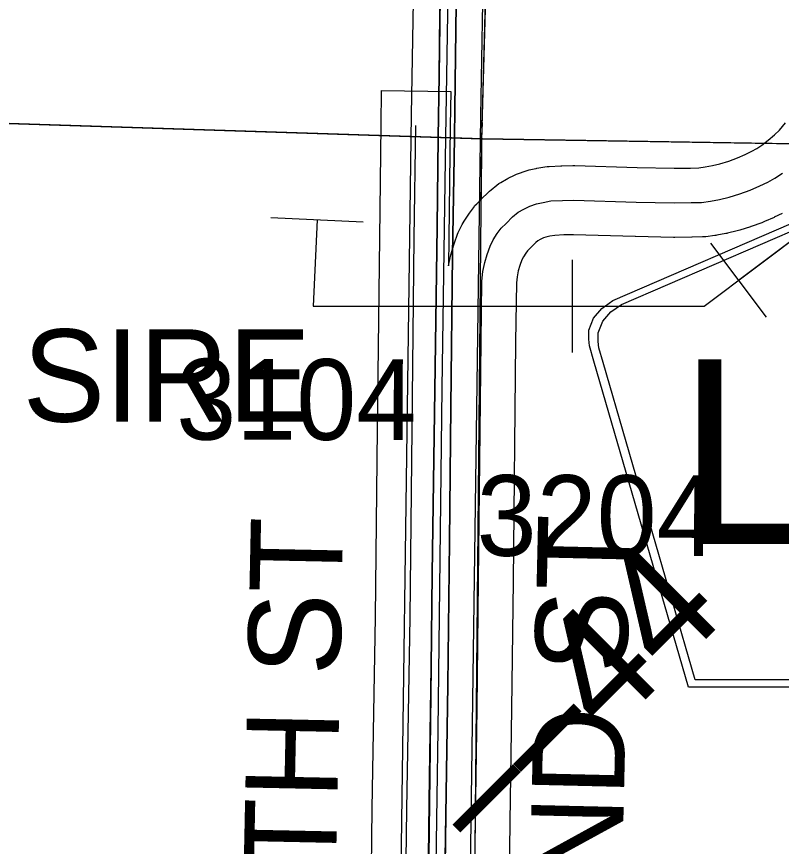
# Model space of a CAD drawing. Extents: x -132.8 to -73.3, y -60 to -26.
# Drawn here: x -121.48 to -120.817, y -55.923 to -55.204 of the extents above; entities that cross this region are included whole.
import ezdxf

# ---------------------------------------------------------------- set-up
doc = ezdxf.new("R2010")
doc.units = 0
for name, color, linetype in [('tdCoCorpBndry', 7, 'Continuous'), ('tdCoDivCarto', 7, 'Continuous'), ('tdCoInt', 7, 'Continuous'), ('tdCoIntCL', 7, 'Continuous'), ('tdCoIntRte', 7, 'Continuous'), ('tdCoPipe', 7, 'Continuous'), ('tdCoPipeTxt', 7, 'Continuous'), ('tdCoPrimary', 7, 'Continuous'), ('tdCoSecRdNmbr', 7, 'Continuous'), ('tdCoSecRdTxt', 7, 'Continuous'), ('tdCoSecRteBand', 7, 'Continuous'), ('tdCoSecRteCL', 7, 'Continuous'), ('tdCoSectLine', 7, 'Continuous'), ('tdCoSectLinePart', 7, 'Continuous'), ('tdCoShieldCoRte', 7, 'Continuous'), ('tdCoSurfAsphalt', 7, 'Continuous'), ('tdCoSurfGravel', 7, 'Continuous'), ('tdCoTwpBndryShd', 7, 'Continuous'), ('tdStHwyIntRefPost1', 7, 'Continuous')]:
    doc.layers.add(name, color=color, linetype=linetype)

msp = doc.modelspace()

# ---------------------------------------------------------------- linework, layer by layer
at = {"layer": 'tdCoCorpBndry'}
msp.add_lwpolyline([(-120.70471, -55.17537), (-120.72184, -55.2041), (-120.75403, -55.25872), (-120.7745, -55.29275), (-120.78919, -55.31424), (-121.07637, -55.30969), (-122.03185, -55.27864), (-122.06321, -55.27827), (-122.07422, -55.18072)], dxfattribs=at)
at = {"layer": 'tdCoDivCarto'}
for p, q in [((-121.11274, -55.15738), (-121.11393, -55.25497)), ((-121.09996, -55.28374), (-121.09875, -55.19277)), ((-121.11393, -55.25497), (-121.11464, -55.3083)), ((-121.10031, -55.30664), (-121.09996, -55.28374)), ((-121.11464, -55.30846), (-121.11566, -55.38567)), ((-121.11464, -55.3083), (-121.11464, -55.30845)), ((-121.11464, -55.30845), (-121.11464, -55.30846)), ((-121.10193, -55.41025), (-121.10035, -55.30892)), ((-121.10035, -55.30892), (-121.10034, -55.3085)), ((-121.10035, -55.30892), (-121.10035, -55.30892)), ((-121.10034, -55.3085), (-121.10031, -55.30664)), ((-121.10034, -55.3085), (-121.10031, -55.30664)), ((-121.11566, -55.38567), (-121.11738, -55.50774)), ((-121.10341, -55.54194), (-121.10193, -55.41025)), ((-121.11738, -55.50774), (-121.11911, -55.6271)), ((-121.10464, -55.65883), (-121.10341, -55.54194)), ((-121.11911, -55.6271), (-121.11985, -55.68678)), ((-121.10612, -55.78312), (-121.10464, -55.65883)), ((-121.11985, -55.68678), (-121.12084, -55.76791)), ((-121.12084, -55.76791), (-121.12207, -55.86261)), ((-121.10785, -55.89582), (-121.10612, -55.78312)), ((-121.12207, -55.86261), (-121.12355, -55.97777)), ((-121.10957, -56.00901), (-121.10785, -55.89582))]:
    msp.add_line(p, q, dxfattribs=at)
for points in [[(-121.11262, -55.14736), (-121.11393, -55.25497), (-121.11464, -55.3083)], [(-121.11262, -55.14736), (-121.11393, -55.25497), (-121.11464, -55.3083)], [(-121.11274, -55.15738), (-121.11393, -55.25497), (-121.11464, -55.3083)], [(-121.10034, -55.3085), (-121.09996, -55.28374), (-121.09875, -55.19277)], [(-121.10034, -55.3085), (-121.09996, -55.28374), (-121.09875, -55.19277)], [(-121.10031, -55.30664), (-121.09996, -55.28374), (-121.09875, -55.19277)], [(-121.11464, -55.30846), (-121.11566, -55.38567), (-121.11738, -55.50774), (-121.11911, -55.6271), (-121.11985, -55.68678), (-121.12084, -55.76791), (-121.12207, -55.86261), (-121.12355, -55.97777), (-121.12503, -56.09713), (-121.12676, -56.2118), (-121.12651, -56.28998), (-121.12644, -56.2918)], [(-121.11464, -55.30846), (-121.11566, -55.38567), (-121.11738, -55.50774), (-121.11911, -55.6271), (-121.11985, -55.68678), (-121.12084, -55.76791), (-121.12207, -55.86261), (-121.12355, -55.97777), (-121.12503, -56.09713), (-121.12676, -56.2118), (-121.12651, -56.28998), (-121.12644, -56.2918)], [(-121.11464, -55.30846), (-121.11566, -55.38567), (-121.11738, -55.50774), (-121.11911, -55.6271), (-121.11985, -55.68678), (-121.12084, -55.76791), (-121.12207, -55.86261), (-121.12355, -55.97777), (-121.12503, -56.09713), (-121.12676, -56.2118), (-121.12651, -56.28998), (-121.12644, -56.2918)], [(-121.11464, -55.3083), (-121.11464, -55.30845), (-121.11464, -55.30846)], [(-121.11464, -55.3083), (-121.11464, -55.30845), (-121.11464, -55.30846)], [(-121.11464, -55.3083), (-121.11464, -55.30845), (-121.11464, -55.30846)], [(-121.11194, -56.29222), (-121.11278, -56.25364), (-121.11155, -56.14933), (-121.10957, -56.00901), (-121.10785, -55.89582), (-121.10612, -55.78312), (-121.10464, -55.65883), (-121.10341, -55.54194), (-121.10193, -55.41025), (-121.10035, -55.30892)], [(-121.11194, -56.29222), (-121.11278, -56.25364), (-121.11155, -56.14933), (-121.10957, -56.00901), (-121.10785, -55.89582), (-121.10612, -55.78312), (-121.10464, -55.65883), (-121.10341, -55.54194), (-121.10193, -55.41025), (-121.10035, -55.30892)], [(-121.11194, -56.29222), (-121.11278, -56.25364), (-121.11155, -56.14933), (-121.10957, -56.00901), (-121.10785, -55.89582), (-121.10612, -55.78312), (-121.10464, -55.65883), (-121.10341, -55.54194), (-121.10193, -55.41025), (-121.10035, -55.30892)], [(-121.10035, -55.30892), (-121.10035, -55.30892), (-121.10034, -55.3085)], [(-121.10035, -55.30892), (-121.10035, -55.30892), (-121.10034, -55.3085)], [(-121.10035, -55.30892), (-121.10035, -55.30892), (-121.10034, -55.3085)]]:
    msp.add_lwpolyline(points, dxfattribs=at)
at = {"layer": 'tdCoInt'}
for points in [[(-121.14184, -56.47033), (-121.14873, -56.31043), (-121.1496, -56.15474), (-121.13788, -55.28894), (-121.13353, -55.04255), (-121.10694, -54.31475)], [(-121.07754, -56.46302), (-121.0866, -56.36086), (-121.08873, -56.30918), (-121.0896, -56.15497), (-121.07788, -55.28991), (-121.07355, -55.04413), (-121.04748, -54.33087)]]:
    msp.add_lwpolyline(points, dxfattribs=at)
at = {"layer": 'tdCoIntCL'}
msp.add_lwpolyline([(-121.11498, -56.39026), (-121.11656, -56.36232), (-121.11786, -56.33063), (-121.11873, -56.3098), (-121.11873, -56.2881), (-121.1196, -56.15486), (-121.11566, -55.88034), (-121.11483, -55.82197), (-121.11135, -55.52597), (-121.10816, -55.30839), (-121.10538, -55.14745), (-121.10354, -55.04334), (-121.09618, -54.83429), (-121.09312, -54.74734), (-121.08618, -54.56897), (-121.0759, -54.28679), (-121.07524, -54.26881), (-121.07524, -54.26881), (-121.06976, -54.11977), (-121.05597, -53.74518), (-121.04104, -53.29303), (-121.03435, -53.13559)], dxfattribs=at)
at = {"layer": 'tdCoIntRte'}
for points in [[(-121.113, -55.14736), (-121.11431, -55.25497), (-121.11501, -55.3083), (-121.11502, -55.30845), (-121.11502, -55.30846), (-121.11604, -55.38567), (-121.11776, -55.50774), (-121.11949, -55.6271), (-121.12023, -55.68678), (-121.12122, -55.76791), (-121.12245, -55.86261), (-121.12393, -55.97777), (-121.12541, -56.09713), (-121.12713, -56.2118), (-121.12689, -56.28813)], [(-121.113, -55.14736), (-121.11431, -55.25497), (-121.11501, -55.3083), (-121.11502, -55.30845), (-121.11502, -55.30846), (-121.11604, -55.38567), (-121.11776, -55.50774), (-121.11949, -55.6271), (-121.12023, -55.68678), (-121.12122, -55.76791), (-121.12245, -55.86261), (-121.12393, -55.97777), (-121.12541, -56.09713), (-121.12713, -56.2118), (-121.12689, -56.28998), (-121.12682, -56.2918)], [(-121.11241, -56.28796), (-121.11316, -56.25364), (-121.11193, -56.14933), (-121.10995, -56.00901), (-121.10823, -55.89582), (-121.1065, -55.78312), (-121.10502, -55.65883), (-121.10379, -55.54194), (-121.10231, -55.41025), (-121.10073, -55.30892), (-121.10073, -55.30892), (-121.10072, -55.3085), (-121.10034, -55.28374), (-121.09913, -55.19277)], [(-121.11232, -56.29222), (-121.11316, -56.25364), (-121.11193, -56.14933), (-121.10995, -56.00901), (-121.10823, -55.89582), (-121.1065, -55.78312), (-121.10502, -55.65883), (-121.10379, -55.54194), (-121.10231, -55.41025), (-121.10073, -55.30892), (-121.10073, -55.30892), (-121.10072, -55.3085), (-121.10034, -55.28374), (-121.09913, -55.19277)]]:
    msp.add_lwpolyline(points, dxfattribs=at)
at = {"layer": 'tdCoPipe'}
for p, q in [((-121.25982, -55.37799), (-121.17974, -55.38163)), ((-120.83007, -55.46438), (-120.87818, -55.40025)), ((-120.99817, -55.49494), (-120.99817, -55.41462))]:
    msp.add_line(p, q, dxfattribs=at)
for points in [[(-121.21972, -55.37981), (-121.22312, -55.45479), (-120.88419, -55.45479), (-120.74793, -55.35255), (-120.59805, -55.35766)], [(-120.85417, -55.43226), (-120.74793, -55.35255), (-120.59805, -55.35766)], [(-121.21972, -55.37981), (-121.22312, -55.45479), (-120.99817, -55.45479)]]:
    msp.add_lwpolyline(points, dxfattribs=at)
at = {"layer": 'tdCoPrimary'}
msp.add_line((-121.10034, -55.3085), (-121.10031, -55.30664), dxfattribs=at)
msp.add_line((-121.10034, -55.3085), (-121.10031, -55.30664), dxfattribs=at)
for points in [[(-121.11274, -55.15738), (-121.11393, -55.25497), (-121.11464, -55.3083), (-121.11464, -55.30845), (-121.11464, -55.30846), (-121.11566, -55.38567), (-121.11738, -55.50774), (-121.11911, -55.6271), (-121.11985, -55.68678), (-121.12084, -55.76791), (-121.12207, -55.86261), (-121.12355, -55.97777), (-121.12503, -56.09713), (-121.12676, -56.2118), (-121.12651, -56.28998), (-121.12644, -56.2918), (-121.12644, -56.2918), (-121.12503, -56.33239), (-121.12209, -56.39006)], [(-121.11274, -55.15738), (-121.11393, -55.25497), (-121.11464, -55.3083)], [(-121.11274, -55.15738), (-121.11393, -55.25497), (-121.11464, -55.3083)], [(-121.10746, -56.39048), (-121.10785, -56.38361), (-121.1113, -56.32171), (-121.11194, -56.29224), (-121.11194, -56.29222), (-121.11278, -56.25364), (-121.11155, -56.14933), (-121.10957, -56.00901), (-121.10785, -55.89582), (-121.10612, -55.78312), (-121.10464, -55.65883), (-121.10341, -55.54194), (-121.10193, -55.41025), (-121.10035, -55.30892), (-121.10035, -55.30892), (-121.10034, -55.3085), (-121.10031, -55.30664), (-121.09996, -55.28374), (-121.09875, -55.19277)], [(-121.10031, -55.30664), (-121.09996, -55.28374), (-121.09875, -55.19277)], [(-121.10031, -55.30664), (-121.09996, -55.28374), (-121.09875, -55.19277)], [(-121.11464, -55.30846), (-121.11566, -55.38567), (-121.11738, -55.50774), (-121.11911, -55.6271), (-121.11985, -55.68678), (-121.12084, -55.76791), (-121.12207, -55.86261), (-121.12355, -55.97777), (-121.12503, -56.09713), (-121.12676, -56.2118), (-121.12651, -56.28998), (-121.12644, -56.2918)], [(-121.11464, -55.30846), (-121.11566, -55.38567), (-121.11738, -55.50774), (-121.11911, -55.6271), (-121.11985, -55.68678), (-121.12084, -55.76791), (-121.12207, -55.86261), (-121.12355, -55.97777), (-121.12503, -56.09713), (-121.12676, -56.2118), (-121.12651, -56.28998), (-121.12644, -56.2918)], [(-121.11464, -55.3083), (-121.11464, -55.30845), (-121.11464, -55.30846)], [(-121.11464, -55.3083), (-121.11464, -55.30845), (-121.11464, -55.30846)], [(-121.11194, -56.29222), (-121.11278, -56.25364), (-121.11155, -56.14933), (-121.10957, -56.00901), (-121.10785, -55.89582), (-121.10612, -55.78312), (-121.10464, -55.65883), (-121.10341, -55.54194), (-121.10193, -55.41025), (-121.10035, -55.30892)], [(-121.11194, -56.29222), (-121.11278, -56.25364), (-121.11155, -56.14933), (-121.10957, -56.00901), (-121.10785, -55.89582), (-121.10612, -55.78312), (-121.10464, -55.65883), (-121.10341, -55.54194), (-121.10193, -55.41025), (-121.10035, -55.30892)], [(-121.10035, -55.30892), (-121.10035, -55.30892), (-121.10034, -55.3085)], [(-121.10035, -55.30892), (-121.10035, -55.30892), (-121.10034, -55.3085)]]:
    msp.add_lwpolyline(points, dxfattribs=at)
at = {"layer": 'tdCoSecRteBand'}
for points in [[(-121.17385, -56.04511), (-121.17188, -55.89036), (-121.17187, -55.89031), (-121.17187, -55.89026), (-121.16916, -55.72438), (-121.16744, -55.56121), (-121.16744, -55.56119), (-121.16744, -55.56117), (-121.16546, -55.39545), (-121.16546, -55.39544), (-121.16546, -55.39543), (-121.16423, -55.29777), (-121.16385, -55.26777), (-121.10386, -55.26853), (-121.10424, -55.29853), (-121.10547, -55.39617), (-121.10575, -55.41985), (-121.1054, -55.41827), (-121.10368, -55.41038), (-121.10345, -55.40932), (-121.10314, -55.40827), (-121.10116, -55.40161), (-121.10089, -55.4007), (-121.10056, -55.39981), (-121.09785, -55.39241), (-121.09727, -55.39083), (-121.09652, -55.38932), (-121.09381, -55.38389), (-121.09311, -55.38251), (-121.09228, -55.3812), (-121.08883, -55.37578), (-121.08828, -55.37491), (-121.08767, -55.37409), (-121.08422, -55.3694), (-121.08288, -55.36759), (-121.08128, -55.36599), (-121.07709, -55.36179), (-121.07142, -55.35612), (-121.07024, -55.35495), (-121.06894, -55.35391), (-121.06401, -55.34996), (-121.06225, -55.34856), (-121.0603, -55.34743), (-121.05562, -55.34471), (-121.05482, -55.34426), (-121.054, -55.34384), (-121.04858, -55.34113), (-121.04685, -55.34027), (-121.04502, -55.33963), (-121.03935, -55.33766), (-121.03763, -55.33706), (-121.03586, -55.33668), (-121.03019, -55.33544), (-121.02964, -55.33532), (-121.02909, -55.33523), (-121.02219, -55.33399), (-121.02029, -55.33366), (-121.01837, -55.33356), (-121.00826, -55.33307), (-121.00792, -55.33305), (-121.00757, -55.33304), (-120.99795, -55.3328), (-120.99709, -55.33277), (-120.99623, -55.3328), (-120.94211, -55.33452), (-120.91004, -55.33525), (-120.896, -55.33501), (-120.88874, -55.33481), (-120.88319, -55.33412), (-120.87688, -55.33293), (-120.87037, -55.3314), (-120.86277, -55.32894), (-120.85524, -55.32629), (-120.84843, -55.32319), (-120.84266, -55.32052), (-120.83851, -55.31819), (-120.83396, -55.31516), (-120.82871, -55.31092), (-120.82303, -55.30626), (-120.81888, -55.30211), (-120.8135, -55.29593)], [(-120.81636, -55.37446), (-120.82327, -55.37767), (-120.82338, -55.37772), (-120.82349, -55.37777), (-120.83163, -55.38147), (-120.83284, -55.38202), (-120.8341, -55.38246), (-120.84322, -55.38566), (-120.84356, -55.38579), (-120.84391, -55.3859), (-120.85303, -55.38886), (-120.85421, -55.38924), (-120.85542, -55.38952), (-120.8638, -55.3915), (-120.86447, -55.39165), (-120.86515, -55.39178), (-120.87304, -55.39326), (-120.87394, -55.39343), (-120.87484, -55.39354), (-120.88274, -55.39453), (-120.88417, -55.39471), (-120.88562, -55.39475), (-120.8945, -55.39499), (-120.89467, -55.395), (-120.89484, -55.395), (-120.90963, -55.39525), (-120.91022, -55.39526), (-120.91081, -55.39524), (-120.94361, -55.3945), (-120.94375, -55.3945), (-120.94388, -55.3945), (-120.99728, -55.3928), (-121.00569, -55.39301), (-121.01353, -55.3934), (-121.01799, -55.39419), (-121.02134, -55.39492), (-121.02348, -55.39566), (-121.02635, -55.3971), (-121.02829, -55.39822), (-121.03017, -55.39972), (-121.03466, -55.40422), (-121.03726, -55.40682), (-121.03876, -55.40886), (-121.04083, -55.41211), (-121.0421, -55.41465), (-121.0439, -55.41957), (-121.0453, -55.42427), (-121.04638, -55.42923), (-121.04686, -55.4346), (-121.04758, -55.48572), (-121.0498, -55.69307), (-121.0498, -55.69307), (-121.0498, -55.69308), (-121.05103, -55.80381), (-121.05103, -55.80387), (-121.05103, -55.80393), (-121.05251, -55.90155), (-121.05473, -56.07488)]]:
    msp.add_lwpolyline(points, dxfattribs=at)
at = {"layer": 'tdCoSecRteCL'}
for points in [[(-121.14765, -56.29087), (-121.14875, -56.25809), (-121.14702, -56.1957), (-121.14385, -56.04562), (-121.14188, -55.89075), (-121.13917, -55.72478), (-121.13744, -55.56153), (-121.13547, -55.39581), (-121.13423, -55.29815)], [(-121.08473, -56.07449), (-121.08251, -55.90113), (-121.08103, -55.80347), (-121.0798, -55.69275), (-121.07758, -55.48535), (-121.07684, -55.43307), (-121.0761, -55.42468), (-121.07437, -55.41679), (-121.0724, -55.41013), (-121.06969, -55.40274), (-121.06697, -55.39731), (-121.06352, -55.39189), (-121.06007, -55.3872), (-121.05588, -55.38301), (-121.0502, -55.37734), (-121.04527, -55.37339), (-121.04059, -55.37068), (-121.03516, -55.36797), (-121.02949, -55.36599), (-121.02382, -55.36476), (-121.01691, -55.36353), (-121.0068, -55.36303), (-120.99718, -55.36279), (-120.94293, -55.36451), (-120.91013, -55.36525), (-120.89534, -55.36501), (-120.88646, -55.36476), (-120.87857, -55.36377), (-120.87067, -55.36229), (-120.86229, -55.36032), (-120.85317, -55.35736), (-120.84404, -55.35415), (-120.8359, -55.35046), (-120.829, -55.34725), (-120.82283, -55.3438), (-120.81617, -55.33936)]]:
    msp.add_lwpolyline(points, dxfattribs=at)
at = {"layer": 'tdCoSectLine'}
for points in [[(-121.07675, -55.30969), (-121.05003, -54.29547)], [(-122.03223, -55.27864), (-121.07675, -55.30969)], [(-121.08617, -56.293), (-121.07675, -55.30969)], [(-121.07675, -55.30969), (-120.07349, -55.32557)]]:
    msp.add_lwpolyline(points, dxfattribs=at)
at = {"layer": 'tdCoSectLinePart'}
for points in [[(-122.03223, -55.27864), (-121.16472, -55.30683)], [(-121.07675, -55.30969), (-121.07638, -55.29557)], [(-121.10475, -55.30878), (-121.07675, -55.30969)], [(-121.07725, -55.36236), (-121.07675, -55.30969)], [(-121.07675, -55.30969), (-120.83285, -55.31355)]]:
    msp.add_lwpolyline(points, dxfattribs=at)
at = {"layer": 'tdCoShieldCoRte'}
for points in [[(-120.89769, -55.78522), (-120.97963, -55.50233), (-120.98351, -55.48917), (-120.98424, -55.48328), (-120.98424, -55.47546), (-120.97999, -55.46515), (-120.97272, -55.45666), (-120.96315, -55.44999), (-120.79587, -55.37764), (-120.78835, -55.37601), (-120.77793, -55.37509), (-120.7675, -55.37601), (-120.75999, -55.37764), (-120.59271, -55.44999), (-120.58314, -55.45666), (-120.57586, -55.46515), (-120.57162, -55.47546), (-120.57162, -55.48328), (-120.57235, -55.48917), (-120.57623, -55.50233), (-120.65817, -55.78522)], [(-120.89183, -55.77889), (-120.97156, -55.50362), (-120.97529, -55.49098), (-120.97598, -55.48534), (-120.97598, -55.47783), (-120.97191, -55.46793), (-120.96493, -55.45978), (-120.95574, -55.45338), (-120.79515, -55.38392), (-120.78794, -55.38235), (-120.77793, -55.38147), (-120.76792, -55.38235), (-120.76071, -55.38392), (-120.60012, -55.45338), (-120.59093, -55.45978), (-120.58395, -55.46793), (-120.57987, -55.47783), (-120.57987, -55.48534), (-120.58057, -55.49098), (-120.5843, -55.50362), (-120.66403, -55.77889)]]:
    msp.add_lwpolyline(points, close=True, dxfattribs=at)
at = {"layer": 'tdCoSurfAsphalt'}
msp.add_lwpolyline([(-121.14299, -56.38944), (-121.14529, -56.35032), (-121.14727, -56.30248), (-121.14765, -56.29087), (-121.14875, -56.25809), (-121.14702, -56.1957), (-121.14385, -56.04562), (-121.14188, -55.89075), (-121.13917, -55.72478), (-121.13744, -55.56153), (-121.13547, -55.39581), (-121.13423, -55.29815)], dxfattribs=at)
at = {"layer": 'tdCoSurfGravel'}
msp.add_lwpolyline([(-121.08473, -56.07449), (-121.08251, -55.90113), (-121.08103, -55.80347), (-121.0798, -55.69275), (-121.07758, -55.48535), (-121.07684, -55.43307), (-121.0761, -55.42468), (-121.07437, -55.41679), (-121.0724, -55.41013), (-121.06969, -55.40274), (-121.06697, -55.39731), (-121.06352, -55.39189), (-121.06007, -55.3872), (-121.05588, -55.38301), (-121.0502, -55.37734), (-121.04527, -55.37339), (-121.04059, -55.37068), (-121.03516, -55.36797), (-121.02949, -55.36599), (-121.02382, -55.36476), (-121.01691, -55.36353), (-121.0068, -55.36303), (-120.99718, -55.36279), (-120.94293, -55.36451), (-120.91013, -55.36525), (-120.89534, -55.36501), (-120.88646, -55.36476), (-120.87857, -55.36377), (-120.87067, -55.36229), (-120.86229, -55.36032), (-120.85317, -55.35736), (-120.84404, -55.35415), (-120.8359, -55.35046), (-120.829, -55.34725), (-120.82283, -55.3438), (-120.81617, -55.33936)], dxfattribs=at)
at = {"layer": 'tdCoTwpBndryShd'}
msp.add_lwpolyline([(-122.06359, -55.27827), (-122.03223, -55.27864), (-121.07675, -55.30969), (-121.05003, -54.29547), (-121.01456, -53.29268), (-121.01115, -53.1722), (-121.00063, -52.80087), (-120.98644, -52.29987), (-120.95707, -51.30108), (-120.93809, -50.82388), (-120.91911, -50.34667), (-120.89993, -49.84653), (-120.88076, -49.34639), (-120.88334, -48.34969), (-120.84389, -47.35854), (-120.84385, -47.34845), (-120.82083, -46.35535), (-120.79273, -45.36236), (-120.75071, -44.39009)], dxfattribs=at)

# ---------------------------------------------------------------- texts
at = {"layer": 'tdCoPipeTxt'}
msp.add_text('SIRE', height=0.08, dxfattribs=at).set_placement((-121.47504, -55.55489))
at = {"layer": 'tdCoSecRdNmbr'}
for s, rotation, p in [('3104', 359.90988, (-121.34195, -55.57048)), ('3204', 359.91004, (-121.08148, -55.67119))]:
    msp.add_text(s, height=0.07, rotation=rotation, dxfattribs=at).set_placement(p)
at = {"layer": 'tdCoSecRdTxt'}
for s, rotation, p in [('189TH ST', 88.8144, (-121.20722, -56.12628)), ('192ND ST', 88.66731, (-120.95962, -56.13604))]:
    msp.add_text(s, height=0.08, rotation=rotation, dxfattribs=at).set_placement(p)
at = {"layer": 'tdCoShieldCoRte'}
msp.add_text('L31', height=0.16, dxfattribs=at).set_placement((-120.90659, -55.66096))
at = {"layer": 'tdStHwyIntRefPost1'}
msp.add_text('‒‒44', height=0.1, rotation=45, dxfattribs=at).set_placement((-121.07291, -55.93383))

doc.saveas('drawing.dxf')
